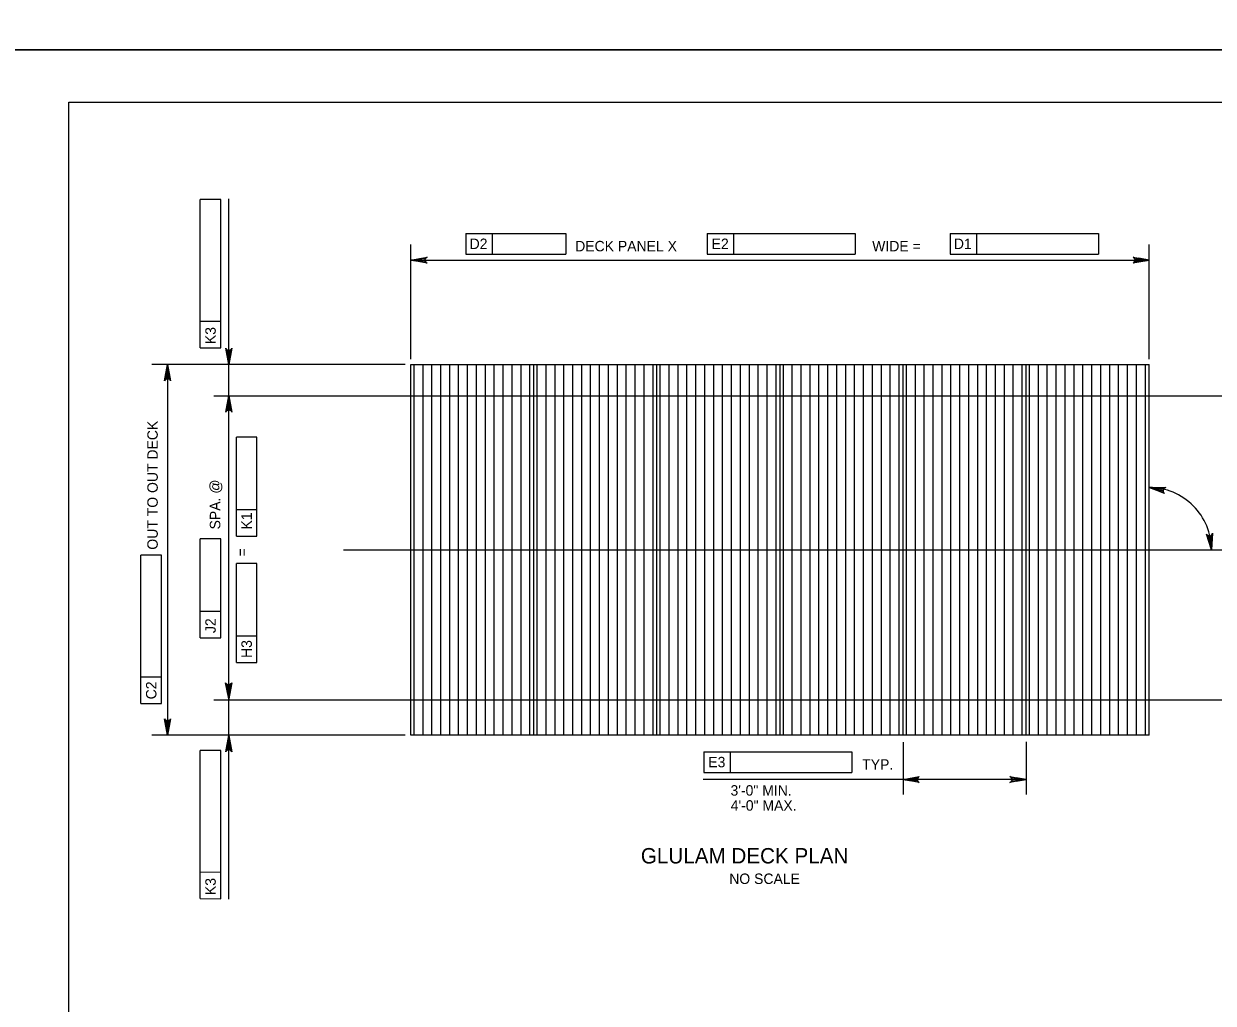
# Model space of a CAD drawing. Extents: x 638175 to 640495, y 294277 to 298435.
# Drawn here: x 639303.6 to 639645, y 295785.9 to 296067 of the extents above; entities that cross this region are included whole.
import ezdxf

# ---------------------------------------------------------------- set-up
doc = ezdxf.new("R2010")
doc.units = 0
for name, color, linetype in [('2', 7, 'Continuous'), ('4', 7, 'Continuous'), ('5', 7, 'Continuous'), ('PLT-BNDY', 7, 'Continuous')]:
    doc.layers.add(name, color=color, linetype=linetype)

msp = doc.modelspace()

# ---------------------------------------------------------------- linework, layer by layer
at = {"layer": '2'}
for p, q in [((639316.46, 295480.46), (639316.46, 296044.46)), ((639316.46, 296044.46), (640102.46, 296044.46)), ((639414.65, 295969.18), (639626.62, 295969.18)), ((639414.65, 295862.88), (639414.65, 295969.18)), ((639449.98, 295862.88), (639449.98, 295969.18)), ((639485.3, 295862.88), (639485.3, 295969.18)), ((639520.63, 295862.88), (639520.63, 295969.18)), ((639555.96, 295862.88), (639555.96, 295969.18)), ((639591.29, 295862.88), (639591.29, 295969.18)), ((639626.62, 295862.88), (639626.62, 295969.18)), ((639626.62, 295862.88), (639414.65, 295862.88))]:
    msp.add_line(p, q, dxfattribs=at)
at = {"layer": '4'}
for p, q in [((639354.22, 295974.01), (639354.22, 296016.53)), ((639360.12, 296016.53), (639354.22, 296016.53)), ((639360.12, 295974.01), (639360.12, 296016.53)), ((639362.43, 295815.8), (639362.43, 296016.77)), ((639430.45, 296006.78), (639459.11, 296006.78)), ((639430.45, 296006.78), (639430.45, 296000.87)), ((639438.01, 296006.78), (639438.01, 296000.87)), ((639459.11, 296006.78), (639459.11, 296000.87)), ((639499.72, 296006.78), (639542.24, 296006.78)), ((639499.72, 296006.78), (639499.72, 296000.87)), ((639507.28, 296006.78), (639507.28, 296000.87)), ((639542.24, 296006.78), (639542.24, 296000.87)), ((639569.5, 296006.78), (639612.02, 296006.78)), ((639569.5, 296006.78), (639569.5, 296000.87)), ((639577.06, 296006.78), (639577.06, 296000.87)), ((639612.02, 296006.78), (639612.02, 296000.87)), ((639414.65, 295970.74), (639414.65, 296003.66)), ((639626.62, 295970.74), (639626.62, 296003.66)), ((639430.45, 296000.87), (639459.11, 296000.87)), ((639499.72, 296000.87), (639542.24, 296000.87)), ((639569.5, 296000.87), (639612.02, 296000.87)), ((639414.65, 295999.16), (639626.62, 295999.16)), ((639360.12, 295981.57), (639354.22, 295981.57)), ((639354.22, 295974.01), (639360.12, 295974.01)), ((639413.08, 295969.18), (639340.34, 295969.18)), ((639344.84, 295969.18), (639344.84, 295862.88)), ((639358.14, 295960.21), (639648.51, 295960.21)), ((639364.58, 295919.91), (639364.58, 295948.31)), ((639370.48, 295948.31), (639364.58, 295948.31)), ((639370.48, 295919.9), (639370.48, 295948.31)), ((639370.48, 295927.46), (639364.58, 295927.47)), ((639354.22, 295890.73), (639354.22, 295919.14)), ((639360.12, 295919.13), (639354.22, 295919.14)), ((639360.12, 295890.73), (639360.12, 295919.13)), ((639364.58, 295919.91), (639370.48, 295919.9)), ((639337.2, 295871.94), (639337.2, 295914.46)), ((639343.11, 295914.46), (639337.2, 295914.46)), ((639343.11, 295871.93), (639343.11, 295914.46)), ((639395.36, 295916.03), (639648.51, 295916.03)), ((639364.58, 295883.68), (639364.58, 295912.08)), ((639370.48, 295912.08), (639364.58, 295912.08)), ((639370.48, 295883.67), (639370.48, 295912.08)), ((639360.12, 295898.29), (639354.22, 295898.3)), ((639354.22, 295890.73), (639360.12, 295890.73)), ((639370.48, 295891.23), (639364.58, 295891.24)), ((639364.58, 295883.68), (639370.48, 295883.67)), ((639343.11, 295879.5), (639337.2, 295879.5)), ((639337.2, 295871.94), (639343.11, 295871.93)), ((639358.14, 295872.94), (639648.51, 295872.94)), ((639413.08, 295862.88), (639340.34, 295862.88)), ((639555.96, 295860.81), (639555.96, 295845.83)), ((639591.29, 295860.88), (639591.28, 295845.83)), ((639354.22, 295815.93), (639354.22, 295858.45)), ((639360.12, 295858.44), (639354.22, 295858.45)), ((639360.12, 295815.92), (639360.12, 295858.44)), ((639498.77, 295858.07), (639541.29, 295858.07)), ((639498.77, 295858.07), (639498.77, 295852.17)), ((639506.33, 295858.07), (639506.33, 295852.17)), ((639541.29, 295858.07), (639541.29, 295852.17)), ((639591.28, 295850.08), (639498.58, 295850.1)), ((639498.77, 295852.17), (639541.29, 295852.17)), ((639360.12, 295823.48), (639354.22, 295823.49)), ((639354.22, 295815.93), (639360.12, 295815.92))]:
    msp.add_line(p, q, dxfattribs=at)
for points in [[(639414.65, 295999.16), (639419.31, 296000.03), (639418.95, 295999.78), (639418.76, 295999.47), (639418.71, 295999.16), (639418.76, 295998.84), (639418.95, 295998.53), (639419.31, 295998.28), (639414.65, 295999.16), (639418.95, 295998.53), (639418.76, 295998.84), (639414.65, 295999.16), (639418.71, 295999.16), (639418.76, 295999.47), (639414.65, 295999.16), (639418.95, 295999.78)], [(639626.62, 295999.16), (639621.96, 295998.28), (639622.31, 295998.53), (639622.5, 295998.84), (639622.55, 295999.16), (639622.5, 295999.47), (639622.31, 295999.78), (639621.96, 296000.03), (639626.62, 295999.16), (639622.31, 295999.78), (639622.5, 295999.47), (639626.62, 295999.16), (639622.55, 295999.16), (639622.5, 295998.84), (639626.62, 295999.16), (639622.31, 295998.53)], [(639362.43, 295969.18), (639361.55, 295973.84), (639361.8, 295973.48), (639362.11, 295973.29), (639362.43, 295973.24), (639362.74, 295973.29), (639363.05, 295973.48), (639363.3, 295973.84), (639362.43, 295969.18), (639363.05, 295973.48), (639362.74, 295973.29), (639362.43, 295969.18), (639362.43, 295973.24), (639362.11, 295973.29), (639362.43, 295969.18), (639361.8, 295973.48)], [(639344.84, 295969.18), (639345.71, 295964.52), (639345.47, 295964.87), (639345.15, 295965.06), (639344.84, 295965.11), (639344.53, 295965.06), (639344.22, 295964.87), (639343.97, 295964.52), (639344.84, 295969.18), (639344.22, 295964.87), (639344.53, 295965.06), (639344.84, 295969.18), (639344.84, 295965.11), (639345.15, 295965.06), (639344.84, 295969.18), (639345.47, 295964.87)], [(639362.43, 295960.21), (639363.3, 295955.55), (639363.05, 295955.91), (639362.74, 295956.09), (639362.43, 295956.15), (639362.11, 295956.09), (639361.8, 295955.91), (639361.55, 295955.55), (639362.43, 295960.21), (639361.8, 295955.91), (639362.11, 295956.09), (639362.43, 295960.21), (639362.43, 295956.15), (639362.74, 295956.09), (639362.43, 295960.21), (639363.05, 295955.91)], [(639626.62, 295933.93), (639631.36, 295933.89), (639630.96, 295933.71), (639630.72, 295933.44), (639630.61, 295933.15), (639630.6, 295932.83), (639630.72, 295932.49), (639631.02, 295932.17), (639626.62, 295933.93), (639630.72, 295932.49), (639630.6, 295932.83), (639626.62, 295933.93), (639630.61, 295933.15), (639630.72, 295933.44), (639626.62, 295933.93), (639630.96, 295933.71)], [(639644.47, 295916.03), (639643.01, 295920.54), (639643.3, 295920.22), (639643.63, 295920.07), (639643.95, 295920.06), (639644.26, 295920.15), (639644.54, 295920.37), (639644.74, 295920.76), (639644.47, 295916.03), (639644.54, 295920.37), (639644.26, 295920.15), (639644.47, 295916.03), (639643.95, 295920.06), (639643.63, 295920.07), (639644.47, 295916.03), (639643.3, 295920.22)], [(639362.38, 295873.23), (639361.5, 295877.89), (639361.75, 295877.53), (639362.07, 295877.34), (639362.38, 295877.29), (639362.69, 295877.34), (639363, 295877.53), (639363.25, 295877.89), (639362.38, 295873.23), (639363, 295877.53), (639362.69, 295877.34), (639362.38, 295873.23), (639362.38, 295877.29), (639362.07, 295877.34), (639362.38, 295873.23), (639361.75, 295877.53)], [(639344.84, 295862.88), (639343.97, 295867.54), (639344.22, 295867.18), (639344.53, 295867), (639344.84, 295866.94), (639345.15, 295867), (639345.47, 295867.18), (639345.71, 295867.54), (639344.84, 295862.88), (639345.47, 295867.18), (639345.15, 295867), (639344.84, 295862.88), (639344.84, 295866.94), (639344.53, 295867), (639344.84, 295862.88), (639344.22, 295867.18)], [(639362.4, 295862.75), (639363.28, 295858.09), (639363.03, 295858.45), (639362.72, 295858.63), (639362.4, 295858.68), (639362.09, 295858.63), (639361.78, 295858.45), (639361.53, 295858.09), (639362.4, 295862.75), (639361.78, 295858.45), (639362.09, 295858.63), (639362.4, 295862.75), (639362.4, 295858.68), (639362.72, 295858.63), (639362.4, 295862.75), (639363.03, 295858.45)], [(639555.96, 295850.09), (639560.62, 295850.96), (639560.26, 295850.71), (639560.07, 295850.4), (639560.02, 295850.09), (639560.07, 295849.77), (639560.26, 295849.46), (639560.62, 295849.21), (639555.96, 295850.09), (639560.26, 295849.46), (639560.07, 295849.77), (639555.96, 295850.09), (639560.02, 295850.09), (639560.07, 295850.4), (639555.96, 295850.09), (639560.26, 295850.71)], [(639591.28, 295850.08), (639586.62, 295849.21), (639586.98, 295849.45), (639587.17, 295849.77), (639587.22, 295850.08), (639587.17, 295850.39), (639586.98, 295850.7), (639586.62, 295850.95), (639591.28, 295850.08), (639586.98, 295850.7), (639587.17, 295850.39), (639591.28, 295850.08), (639587.22, 295850.08), (639587.17, 295849.77), (639591.28, 295850.08), (639586.98, 295849.45)]]:
    msp.add_lwpolyline(points, dxfattribs=at)
for points in [[(639417.65, 295999.66), (639417.65, 295998.66), (639414.65, 295999.16)], [(639623.62, 295999.66), (639623.62, 295998.66), (639626.62, 295999.16)], [(639362.92, 295972.13), (639361.93, 295972.13), (639362.43, 295969.18)], [(639344.34, 295966.18), (639345.34, 295966.18), (639344.84, 295969.18)], [(639362.92, 295957.26), (639361.93, 295957.26), (639362.43, 295960.21)], [(639362.92, 295875.89), (639361.93, 295875.89), (639362.43, 295872.94)], [(639344.34, 295865.88), (639345.34, 295865.88), (639344.84, 295862.88)], [(639362.92, 295859.93), (639361.93, 295859.93), (639362.43, 295862.88)], [(639558.79, 295850.56), (639558.79, 295849.61), (639555.96, 295850.09)], [(639588.45, 295850.55), (639588.45, 295849.61), (639591.28, 295850.08)]]:
    msp.add_lwpolyline(points, close=True, dxfattribs=at)
msp.add_arc((639626.62, 295916.03), 17.85, 0.0023, 90.0027, dxfattribs=at)
at = {"layer": '5'}
for p, q in [((639415.6, 295862.88), (639415.6, 295969.18)), ((639418.16, 295862.88), (639418.16, 295969.18)), ((639420.72, 295862.88), (639420.72, 295969.18)), ((639423.28, 295862.88), (639423.28, 295969.18)), ((639425.83, 295862.88), (639425.83, 295969.18)), ((639428.39, 295862.88), (639428.39, 295969.18)), ((639430.95, 295862.88), (639430.95, 295969.18)), ((639433.5, 295862.88), (639433.5, 295969.18)), ((639436.06, 295862.88), (639436.06, 295969.18)), ((639438.62, 295862.88), (639438.62, 295969.18)), ((639441.18, 295862.88), (639441.18, 295969.18)), ((639443.73, 295862.88), (639443.73, 295969.18)), ((639446.29, 295862.88), (639446.29, 295969.18)), ((639448.85, 295862.88), (639448.85, 295969.18)), ((639450.93, 295862.88), (639450.93, 295969.18)), ((639453.49, 295862.88), (639453.49, 295969.18)), ((639456.05, 295862.88), (639456.05, 295969.18)), ((639458.6, 295862.88), (639458.6, 295969.18)), ((639461.16, 295862.88), (639461.16, 295969.18)), ((639463.72, 295862.88), (639463.72, 295969.18)), ((639466.28, 295862.88), (639466.28, 295969.18)), ((639468.83, 295862.88), (639468.83, 295969.18)), ((639471.39, 295862.88), (639471.39, 295969.18)), ((639473.95, 295862.88), (639473.95, 295969.18)), ((639476.51, 295862.88), (639476.51, 295969.18)), ((639479.06, 295862.88), (639479.06, 295969.18)), ((639481.62, 295862.88), (639481.62, 295969.18)), ((639484.18, 295862.88), (639484.18, 295969.18)), ((639486.26, 295862.88), (639486.26, 295969.18)), ((639488.82, 295862.88), (639488.82, 295969.18)), ((639491.38, 295862.88), (639491.38, 295969.18)), ((639493.93, 295862.88), (639493.93, 295969.18)), ((639496.49, 295862.88), (639496.49, 295969.18)), ((639499.05, 295862.88), (639499.05, 295969.18)), ((639501.61, 295862.88), (639501.61, 295969.18)), ((639504.16, 295862.88), (639504.16, 295969.18)), ((639506.72, 295862.88), (639506.72, 295969.18)), ((639509.28, 295862.88), (639509.28, 295969.18)), ((639511.83, 295862.88), (639511.83, 295969.18)), ((639514.39, 295862.88), (639514.39, 295969.18)), ((639516.95, 295862.88), (639516.95, 295969.18)), ((639519.51, 295862.88), (639519.51, 295969.18)), ((639521.59, 295862.88), (639521.59, 295969.18)), ((639524.15, 295862.88), (639524.15, 295969.18)), ((639526.7, 295862.88), (639526.7, 295969.18)), ((639529.26, 295862.88), (639529.26, 295969.18)), ((639531.82, 295862.88), (639531.82, 295969.18)), ((639534.38, 295862.88), (639534.38, 295969.18)), ((639536.93, 295862.88), (639536.93, 295969.18)), ((639539.49, 295862.88), (639539.49, 295969.18)), ((639542.05, 295862.88), (639542.05, 295969.18)), ((639544.61, 295862.88), (639544.61, 295969.18)), ((639547.16, 295862.88), (639547.16, 295969.18)), ((639549.72, 295862.88), (639549.72, 295969.18)), ((639552.28, 295862.88), (639552.28, 295969.18)), ((639554.83, 295862.88), (639554.83, 295969.18)), ((639556.92, 295862.88), (639556.92, 295969.18)), ((639559.48, 295862.88), (639559.48, 295969.18)), ((639562.03, 295862.88), (639562.03, 295969.18)), ((639564.59, 295862.88), (639564.59, 295969.18)), ((639567.15, 295862.88), (639567.15, 295969.18)), ((639569.7, 295862.88), (639569.7, 295969.18)), ((639572.26, 295862.88), (639572.26, 295969.18)), ((639574.82, 295862.88), (639574.82, 295969.18)), ((639577.38, 295862.88), (639577.38, 295969.18)), ((639579.93, 295862.88), (639579.93, 295969.18)), ((639582.49, 295862.88), (639582.49, 295969.18)), ((639585.05, 295862.88), (639585.05, 295969.18)), ((639587.6, 295862.88), (639587.6, 295969.18)), ((639590.16, 295862.88), (639590.16, 295969.18)), ((639592.25, 295862.88), (639592.25, 295969.18)), ((639594.8, 295862.88), (639594.8, 295969.18)), ((639597.36, 295862.88), (639597.36, 295969.18)), ((639599.92, 295862.88), (639599.92, 295969.18)), ((639602.47, 295862.88), (639602.47, 295969.18)), ((639605.03, 295862.88), (639605.03, 295969.18)), ((639607.59, 295862.88), (639607.59, 295969.18)), ((639610.15, 295862.88), (639610.15, 295969.18)), ((639612.7, 295862.88), (639612.7, 295969.18)), ((639615.26, 295862.88), (639615.26, 295969.18)), ((639617.82, 295862.88), (639617.82, 295969.18)), ((639620.37, 295862.88), (639620.37, 295969.18)), ((639622.93, 295862.88), (639622.93, 295969.18)), ((639625.49, 295862.88), (639625.49, 295969.18))]:
    msp.add_line(p, q, dxfattribs=at)
at = {"layer": 'PLT-BNDY'}
for points in [[(639276.46, 296653.46), (640117.46, 296653.46), (640117.46, 296059.46), (639276.46, 296059.46)], [(639276.46, 296059.46), (640117.46, 296059.46), (640117.46, 295465.46), (639276.46, 295465.46)]]:
    msp.add_lwpolyline(points, close=True, dxfattribs=at)

# ---------------------------------------------------------------- texts
at = {"layer": '4'}
for s, rotation, p in [('D2', 359.9382, (639431.53, 296002.33)), ('E2', 359.9382, (639501.01, 296002.33)), ('D1', 359.9382, (639570.53, 296002.33)), ('K3', 89.9382, (639358.67, 295975.04)), ('OUT TO OUT DECK', 90, (639342.03, 295916.06)), ('SPA. @', 90, (639359.97, 295921.87)), ('K1', 89.9382, (639369.03, 295921.83)), ('=', 90, (639367.7, 295914.11)), ('J2', 89.9382, (639358.67, 295892.13)), ('H3', 89.9382, (639369.03, 295884.99)), ('C2', 89.9382, (639341.65, 295873.12)), ('E3', 359.9382, (639500.05, 295853.62)), ('TYP.', 359.9382, (639544.22, 295852.92)), ('K3', 89.9382, (639358.67, 295816.95))]:
    msp.add_text(s, height=3, rotation=rotation, dxfattribs=at).set_placement(p)
for s, height, p in [('DECK PANEL X', 3, (639461.84, 296001.66)), ('WIDE =', 3, (639547.09, 296001.66)), ('3\'-0" MIN.', 3, (639506.42, 295845.49)), ('3\'-0" MIN.', 3, (639506.42, 295845.49)), ('4\'-0" MAX.', 3, (639506.48, 295841.17)), ('GLULAM DECK PLAN', 4.4292, (639480.68, 295826.02)), ('NO SCALE', 3, (639506.06, 295820.14))]:
    msp.add_text(s, height=height, dxfattribs=at).set_placement(p)

doc.saveas('drawing.dxf')
